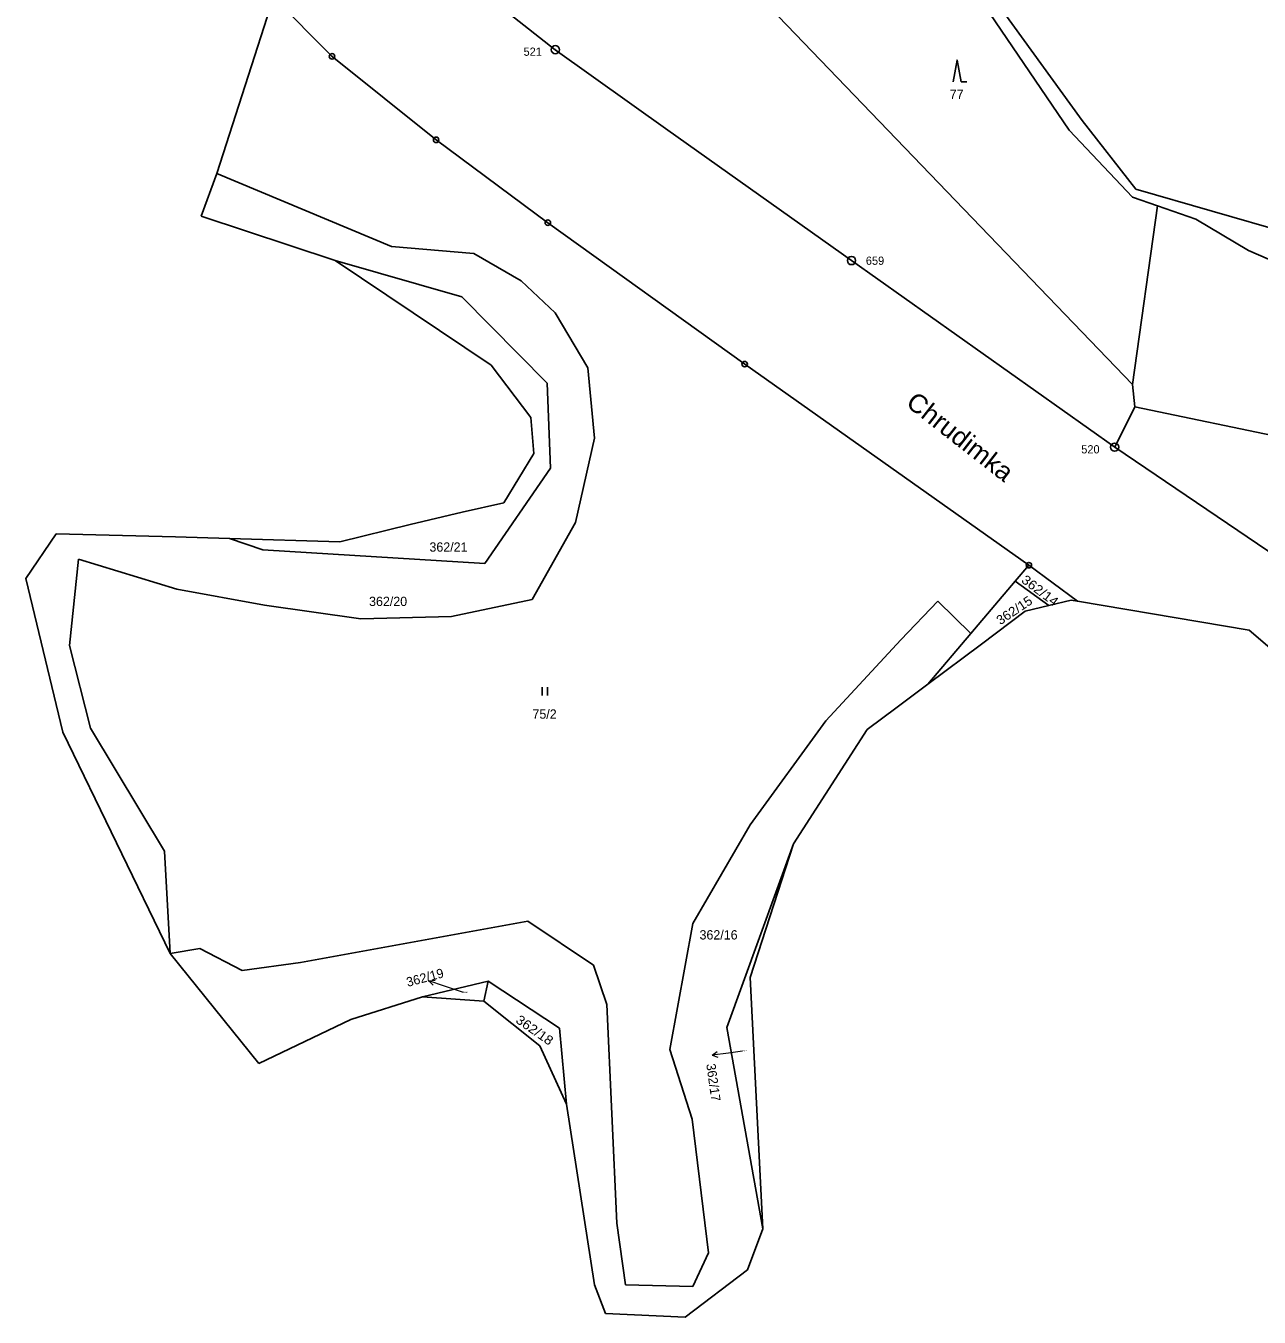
# Model space of a CAD drawing. Extents: x -645290 to -643454, y -1064771 to -1062356.
# Drawn here: x -645279.9 to -645054.6, y -1063822.7 to -1063586.8 of the extents above; entities that cross this region are included whole.
import ezdxf
from ezdxf.enums import TextEntityAlignment as Align

# ---------------------------------------------------------------- set-up
doc = ezdxf.new("R2010")
doc.units = 0
doc.header["$LTSCALE"] = 0.68
for name, color, linetype, lineweight in [('1', 7, 'Continuous', 25), ('3', 7, 'Continuous', 25), ('7', 7, 'Continuous', 13), ('8', 7, 'Continuous', 25)]:
    doc.layers.add(name, color=color, linetype=linetype, lineweight=lineweight)
doc.layers.add('2', color=7, linetype='Continuous')

msp = doc.modelspace()

# ---------------------------------------------------------------- linework, layer by layer
at = {"layer": '1'}
for p, q in [((-645126.67, -1063549.25), (-645086.95, -1063604.1)), ((-645089.31, -1063605.87), (-645110.18, -1063575.16)), ((-645183.2, -1063591.19), (-645200.19, -1063577.83)), ((-645234.68, -1063581.63), (-645245.04, -1063613.82)), ((-645223.98, -1063592.42), (-645234.68, -1063581.63)), ((-645077.76, -1063652.37), (-645145.5, -1063581.86)), ((-645162.61, -1063605.87), (-645183.2, -1063591.19)), ((-645204.97, -1063607.66), (-645223.98, -1063592.42)), ((-645077.13, -1063616.7), (-645086.95, -1063604.1)), ((-645184.56, -1063622.8), (-645204.97, -1063607.66)), ((-645129.09, -1063629.71), (-645162.61, -1063605.87)), ((-645077.76, -1063618.14), (-645089.31, -1063605.87)), ((-645245.04, -1063613.82), (-645247.87, -1063621.63)), ((-645213.1, -1063627.17), (-645245.04, -1063613.82)), ((-645077.13, -1063616.7), (-645036.68, -1063628.33)), ((-645073.19, -1063619.74), (-645077.76, -1063618.14)), ((-645073.19, -1063619.74), (-645077.76, -1063652.37)), ((-645066.2, -1063622.17), (-645073.19, -1063619.74)), ((-645247.87, -1063621.63), (-645223.39, -1063629.69)), ((-645148.6, -1063648.63), (-645184.56, -1063622.8)), ((-645056.54, -1063627.86), (-645066.2, -1063622.17)), ((-645198.06, -1063628.44), (-645213.1, -1063627.17)), ((-645189.46, -1063633.39), (-645198.06, -1063628.44)), ((-645048.68, -1063631.3), (-645056.54, -1063627.86)), ((-645223.39, -1063629.69), (-645200.29, -1063636.35)), ((-645223.39, -1063629.69), (-645194.91, -1063648.83)), ((-645183.2, -1063639.26), (-645189.46, -1063633.39)), ((-645200.29, -1063636.35), (-645184.67, -1063652.12)), ((-645177.23, -1063649.33), (-645183.2, -1063639.26)), ((-645194.91, -1063648.83), (-645187.68, -1063658.36)), ((-645176.02, -1063662.15), (-645177.23, -1063649.33)), ((-645096.68, -1063685.36), (-645148.6, -1063648.63)), ((-645184.67, -1063652.12), (-645184.07, -1063667.61)), ((-645077.76, -1063652.37), (-645077.33, -1063656.4)), ((-645035.11, -1063665.23), (-645077.33, -1063656.4)), ((-645187.68, -1063658.36), (-645187.1, -1063664.97)), ((-645179.49, -1063677.56), (-645176.02, -1063662.15)), ((-645040.74, -1063691.07), (-645081, -1063663.79)), ((-645187.1, -1063664.97), (-645192.58, -1063673.98)), ((-645184.07, -1063667.61), (-645196.08, -1063685.07)), ((-645192.58, -1063673.98), (-645200.22, -1063675.64)), ((-645200.22, -1063675.64), (-645209.7, -1063677.9)), ((-645209.7, -1063677.9), (-645222.55, -1063681.08)), ((-645187.45, -1063691.63), (-645179.49, -1063677.56)), ((-645274.39, -1063679.65), (-645279.93, -1063687.76)), ((-645252.57, -1063680.2), (-645274.39, -1063679.65)), ((-645252.57, -1063680.2), (-645242.72, -1063680.49)), ((-645236.63, -1063682.54), (-645242.72, -1063680.49)), ((-645222.55, -1063681.08), (-645242.72, -1063680.49)), ((-645196.08, -1063685.07), (-645236.63, -1063682.54)), ((-645271.92, -1063700.01), (-645270.32, -1063684.26)), ((-645270.32, -1063684.26), (-645252.32, -1063689.74)), ((-645096.68, -1063685.36), (-645099.16, -1063688.28)), ((-645087.77, -1063691.94), (-645096.68, -1063685.36)), ((-645279.93, -1063687.76), (-645273.17, -1063715.87)), ((-645252.32, -1063689.74), (-645236.3, -1063692.63)), ((-645099.16, -1063688.28), (-645107.29, -1063697.85)), ((-645099.16, -1063688.28), (-645093.03, -1063692.72)), ((-645236.3, -1063692.63), (-645218.73, -1063695.14)), ((-645202.15, -1063694.7), (-645187.45, -1063691.63)), ((-645113.33, -1063691.94), (-645120.08, -1063699)), ((-645107.29, -1063697.85), (-645113.33, -1063691.94)), ((-645097.37, -1063693.76), (-645093.03, -1063692.72)), ((-645093.03, -1063692.72), (-645088.98, -1063691.74)), ((-645088.98, -1063691.74), (-645087.77, -1063691.94)), ((-645087.77, -1063691.94), (-645056.41, -1063697.24)), ((-645218.73, -1063695.14), (-645202.15, -1063694.7)), ((-645105.36, -1063699.76), (-645097.37, -1063693.76)), ((-645056.41, -1063697.24), (-645040.92, -1063710.61)), ((-645120.08, -1063699), (-645133.77, -1063713.8)), ((-645107.29, -1063697.85), (-645115.13, -1063707.08)), ((-645105.36, -1063699.76), (-645115.13, -1063707.08)), ((-645268.13, -1063715.15), (-645271.92, -1063700.01)), ((-645120.75, -1063711.3), (-645115.13, -1063707.08)), ((-645126.2, -1063715.39), (-645120.75, -1063711.3)), ((-645133.77, -1063713.8), (-645147.57, -1063732.79)), ((-645273.17, -1063715.87), (-645253.53, -1063756.31)), ((-645254.62, -1063737.6), (-645268.13, -1063715.15)), ((-645139.67, -1063736.26), (-645126.2, -1063715.39)), ((-645147.57, -1063732.79), (-645158.08, -1063750.83)), ((-645253.53, -1063756.31), (-645254.62, -1063737.6)), ((-645139.67, -1063736.26), (-645151.83, -1063769.82)), ((-645147.58, -1063760.69), (-645139.67, -1063736.26)), ((-645188.23, -1063750.4), (-645229.73, -1063757.92)), ((-645176.22, -1063758.44), (-645188.23, -1063750.4)), ((-645158.08, -1063750.83), (-645162.27, -1063773.82)), ((-645248.16, -1063755.34), (-645253.53, -1063756.31)), ((-645253.53, -1063756.31), (-645237.39, -1063776.38)), ((-645240.4, -1063759.4), (-645248.16, -1063755.34)), ((-645229.73, -1063757.92), (-645240.4, -1063759.4)), ((-645173.77, -1063765.57), (-645176.22, -1063758.44)), ((-645145.27, -1063806.57), (-645147.58, -1063760.69)), ((-645207.44, -1063764.2), (-645195.47, -1063761.32)), ((-645195.47, -1063761.32), (-645196.23, -1063765.01)), ((-645195.47, -1063761.32), (-645182.4, -1063769.91)), ((-645220.58, -1063768.35), (-645207.44, -1063764.2)), ((-645207.44, -1063764.2), (-645196.23, -1063765.01)), ((-645196.23, -1063765.01), (-645186.01, -1063773.14)), ((-645171.96, -1063805.53), (-645173.77, -1063765.57)), ((-645237.39, -1063776.38), (-645220.58, -1063768.35)), ((-645182.4, -1063769.91), (-645181.16, -1063783.81)), ((-645151.83, -1063769.82), (-645145.27, -1063806.57)), ((-645186.01, -1063773.14), (-645181.16, -1063783.81)), ((-645162.27, -1063773.82), (-645158.22, -1063786.52)), ((-645181.16, -1063783.81), (-645176.02, -1063816.78)), ((-645158.22, -1063786.52), (-645155.22, -1063810.96)), ((-645170.37, -1063816.81), (-645171.96, -1063805.53)), ((-645148.11, -1063814.06), (-645145.27, -1063806.57)), ((-645155.22, -1063810.96), (-645158.06, -1063817.08)), ((-645159.48, -1063822.71), (-645148.11, -1063814.06)), ((-645176.02, -1063816.78), (-645174.03, -1063822.04)), ((-645158.06, -1063817.08), (-645170.37, -1063816.81)), ((-645174.03, -1063822.04), (-645159.48, -1063822.71))]:
    msp.add_line(p, q, dxfattribs=at)
msp.add_lwpolyline([(-645077.33, -1063656.4), (-645081, -1063663.79), (-645129.09, -1063629.71)], dxfattribs=at)
at = {"layer": '3'}
for p, q in [((-645109.03, -1063597.08), (-645108.034, -1063597.08)), ((-645185.611, -1063709.15), (-645185.611, -1063707.65)), ((-645184.61, -1063709.15), (-645184.61, -1063707.65))]:
    msp.add_line(p, q, dxfattribs=at)
msp.add_lwpolyline([(-645109.03, -1063597.08), (-645109.78, -1063593.08), (-645110.53, -1063597.08)], dxfattribs=at)
at = {"layer": '7'}
for p, q in [((-645206.277, -1063761.293), (-645205.494, -1063762.092)), ((-645154.529, -1063774.826), (-645153.474, -1063775.201))]:
    msp.add_line(p, q, dxfattribs=at)
for points in [[(-645199.98, -1063763.43), (-645203.44, -1063762.27), (-645206.277, -1063761.293), (-645205.168, -1063761.146)], [(-645148.98, -1063774.13), (-645151.55, -1063774.46), (-645154.529, -1063774.826), (-645153.596, -1063774.207)]]:
    msp.add_lwpolyline(points, dxfattribs=at)
at = {"layer": '8'}
for centre, radius in [((-645183.2, -1063591.1898), 0.75), ((-645183.2, -1063591.1898), 0.03), ((-645223.98, -1063592.4199), 0.5), ((-645223.98, -1063592.4199), 0.0303), ((-645204.97, -1063607.6599), 0.5), ((-645204.97, -1063607.6599), 0.0303), ((-645184.56, -1063622.7999), 0.5), ((-645184.56, -1063622.7999), 0.0303), ((-645129.09, -1063629.7098), 0.75), ((-645129.09, -1063629.7098), 0.03), ((-645148.6, -1063648.6299), 0.5), ((-645148.6, -1063648.6299), 0.0303), ((-645081, -1063663.7898), 0.75), ((-645081, -1063663.7898), 0.03), ((-645096.68, -1063685.3599), 0.5), ((-645096.68, -1063685.3599), 0.0303)]:
    msp.add_circle(centre, radius, dxfattribs=at)

# ---------------------------------------------------------------- texts
at = {"layer": '2'}
for s, p in [('77', (-645109.879, -1063600.205)), ('362/16', (-645153.37, -1063753.725))]:
    msp.add_text(s, height=1.7, dxfattribs=at).set_placement(p, align=Align.CENTER)
for s, height, p in [('362/21', 1.7, (-645206.19, -1063682.885)), ('362/20', 1.7, (-645217.22, -1063692.814)), ('75/2', 1.7, (-645187.37, -1063713.395)), ('362/19', 0.2, (-645199.98, -1063763.479)), ('362/17', 0.2, (-645148.98, -1063774.179))]:
    msp.add_text(s, height=height, dxfattribs=at).set_placement(p)
at = {"layer": '2', "width": 1.1}
msp.add_text('362/14', height=1.7, rotation=323, dxfattribs=at).set_placement((-645095.145, -1063690.6655), align=Align.CENTER)
at = {"layer": '2'}
for s, rotation, width, p in [('362/15', 34, 1.05, (-645101.892, -1063696.342)), ('362/18', 325, 1.1, (-645190.583, -1063768.778))]:
    msp.add_text(s, height=1.7, rotation=rotation, dxfattribs=dict(at, width=width)).set_placement(p)
for s, rotation, p in [('362/19', 15, (-645203.435, -1063760.5895)), ('362/17', 278, (-645154.6633, -1063783.3984))]:
    msp.add_text(s, height=1.7, rotation=rotation, dxfattribs=at).set_placement(p, align=Align.RIGHT)
at = {"layer": '7', "width": 1.05}
msp.add_text('Chrudimka', height=3.4, rotation=322, dxfattribs=at).set_placement((-645110.2596, -1063663.2057), align=Align.CENTER)
at = {"layer": '8'}
for s, p in [('521', (-645185.649, -1063592.307)), ('520', (-645083.759, -1063664.937))]:
    msp.add_text(s, height=1.5, dxfattribs=at).set_placement(p, align=Align.RIGHT)
msp.add_text('659', height=1.5, dxfattribs=at).set_placement((-645126.46, -1063630.485))

doc.saveas('drawing.dxf')
